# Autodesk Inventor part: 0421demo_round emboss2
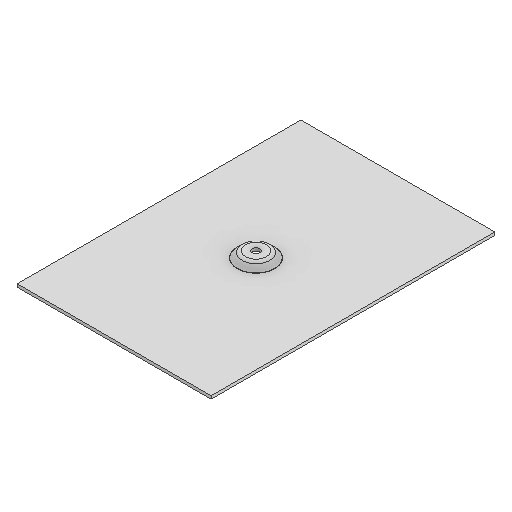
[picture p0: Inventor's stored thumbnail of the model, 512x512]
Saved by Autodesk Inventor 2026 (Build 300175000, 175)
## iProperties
Created: 2025-03
Part Number: 0421demo_round emboss2
Material: Generic
Document SubType Name: Sheet Metal
Designer: zhangy5
Density: 1 g/cm^3
Sheet Metal Rule: Default
Appearance: Default
Author: zhangy5
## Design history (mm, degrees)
node "Face1"
  sketch "Sketch1"
    geometry: L1 (99.185, 145.092)-(-99.185, 145.092); L2 (-99.185, 145.092)-(-99.185, -145.092); L3 (-99.185, -145.092)-(99.185, -145.092); L4 (99.185, -145.092)-(99.185, 145.092); L5 (99.185, 145.092)-(-99.185, -145.092); L6 (-99.185, 145.092)-(99.185, -145.092); 1 further point
    constraints: 12 end point, 2 midpoint, 2 parallel, 1 horizontal, 1 perpendicular
sketch "Sketch2"
  geometry: L1 (-12.7, 0)-(12.7, 0); L2 (0, -12.7)-(0, 12.7); C1 r 3.81 at (0, 0); A1 r 12.7 centre (0, 0) between (-12.7, 0) and (12.7, 0); 2 further points
  constraints: 4 end point, 4 point on circle, 3 coincident, 2 centre point, 1 horizontal, 1 vertical
  dimensions: "Diameter" = 25.4 diameter of A1; "Inner_Diameter" = 7.62 diameter of C1
extrude "Extrusion1" join sketch "Sketch2" taper "d3" = 0 deg; distance "Height" = 6.35
workplane "Work Plane1"
sketch "Sketch4"
  geometry: C1 r 12.7 at (0, 0)
  constraints: 1 centre point
  dimensions: "d6" = 25.4 diameter of C1 (= Diameter)
extrude "Extrusion2" join sketch "Sketch4" distance "d7" = 6.35 (= Height); taper "Angle" = 45 deg
sketch "Sketch3"
  geometry: C1 r 12.7 at (0, 0)
  constraints: 1 centre point
  dimensions: "d5" = 25.4 diameter of C1 (= Diameter)
extrude "Extrusion3" cut sketch "Sketch3" distance "d9" = 6.35 (= Height); taper "d10" = 45 deg (= Angle)
extrude "Extrusion5" cut sketch "Sketch2" stored distance "d29" = 0; taper "d30" = 0 deg
fillet "Fillet1" dims "d14" = 0.381, "d20" = 5.08 (= Top_Fillet), "Top_Fillet" = 5.08
sketch "Sketch6"
  geometry: C1 r 12.7 at (0, 0); C2 r 3.81 at (0, 0); 3 further points
  constraints: 4 coincident, 2 centre point
  dimensions: "d18" = 25.4 diameter of C1 (= Diameter); "d19" = 7.62 diameter of C2 (= Top_Diameter)
body "Solid1"
face "Plate1" dims "d0" = 3.048 (= Thickness)
other parameters: "Thickness" = 3.048, "BendRadius" = 3.048 (= Thickness), "BendReliefWidth" = 3.048 (= Thickness), "BendReliefDepth" = 1.524 (= 0.5 x Thickness), "CornerReliefSize" = 12.192 (= 4 x Thickness), "SeamGap" = 0.00508, "MinimumRemnant" = 6.096 (= 2 x Thickness), "TransitionRadius" = 3.048 (= BendRadius), "JacobiRadiusSize" = 3.048 (= BendRadius), "GapSize" = 3.048 (= Thickness), "d4" = -3.048 (= -Thickness), "Top_Diameter" = 7.62
